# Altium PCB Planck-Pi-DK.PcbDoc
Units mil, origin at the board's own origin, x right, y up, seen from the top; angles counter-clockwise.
Board outline 1820 x 940 mil, 4 copper layers (Top1, Signal2, Gnd3, Bottom4), stack 60.449 mil thick; 99 components, 92 nets, 414 pads, 228 vias.
Unrouted connection lines stored in the file: 54.
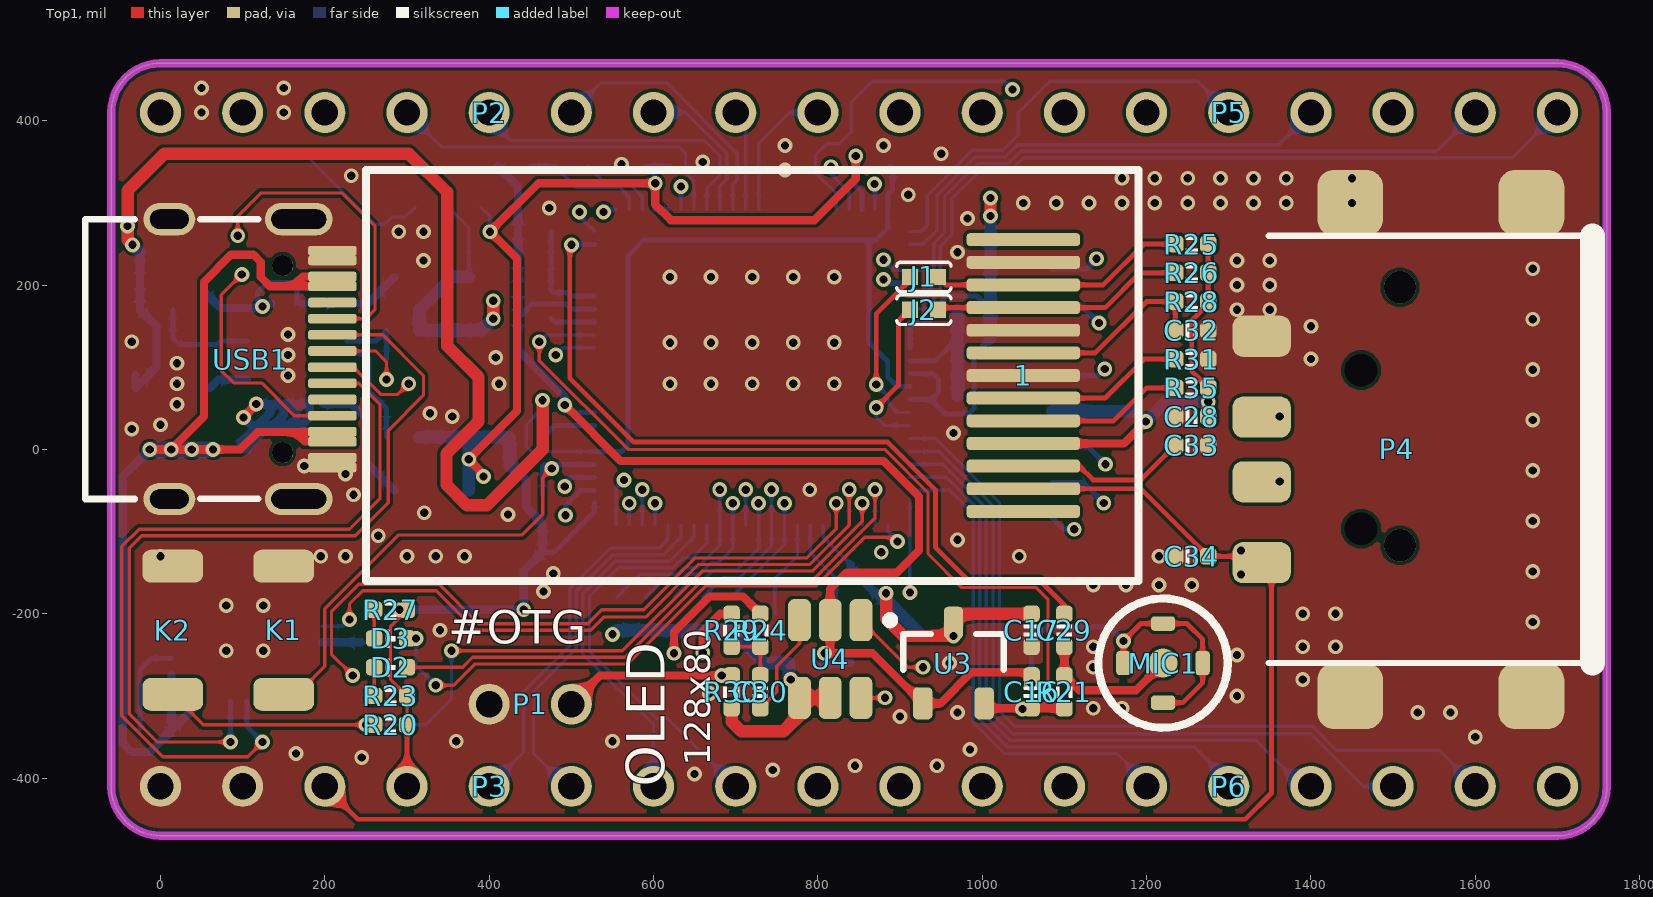
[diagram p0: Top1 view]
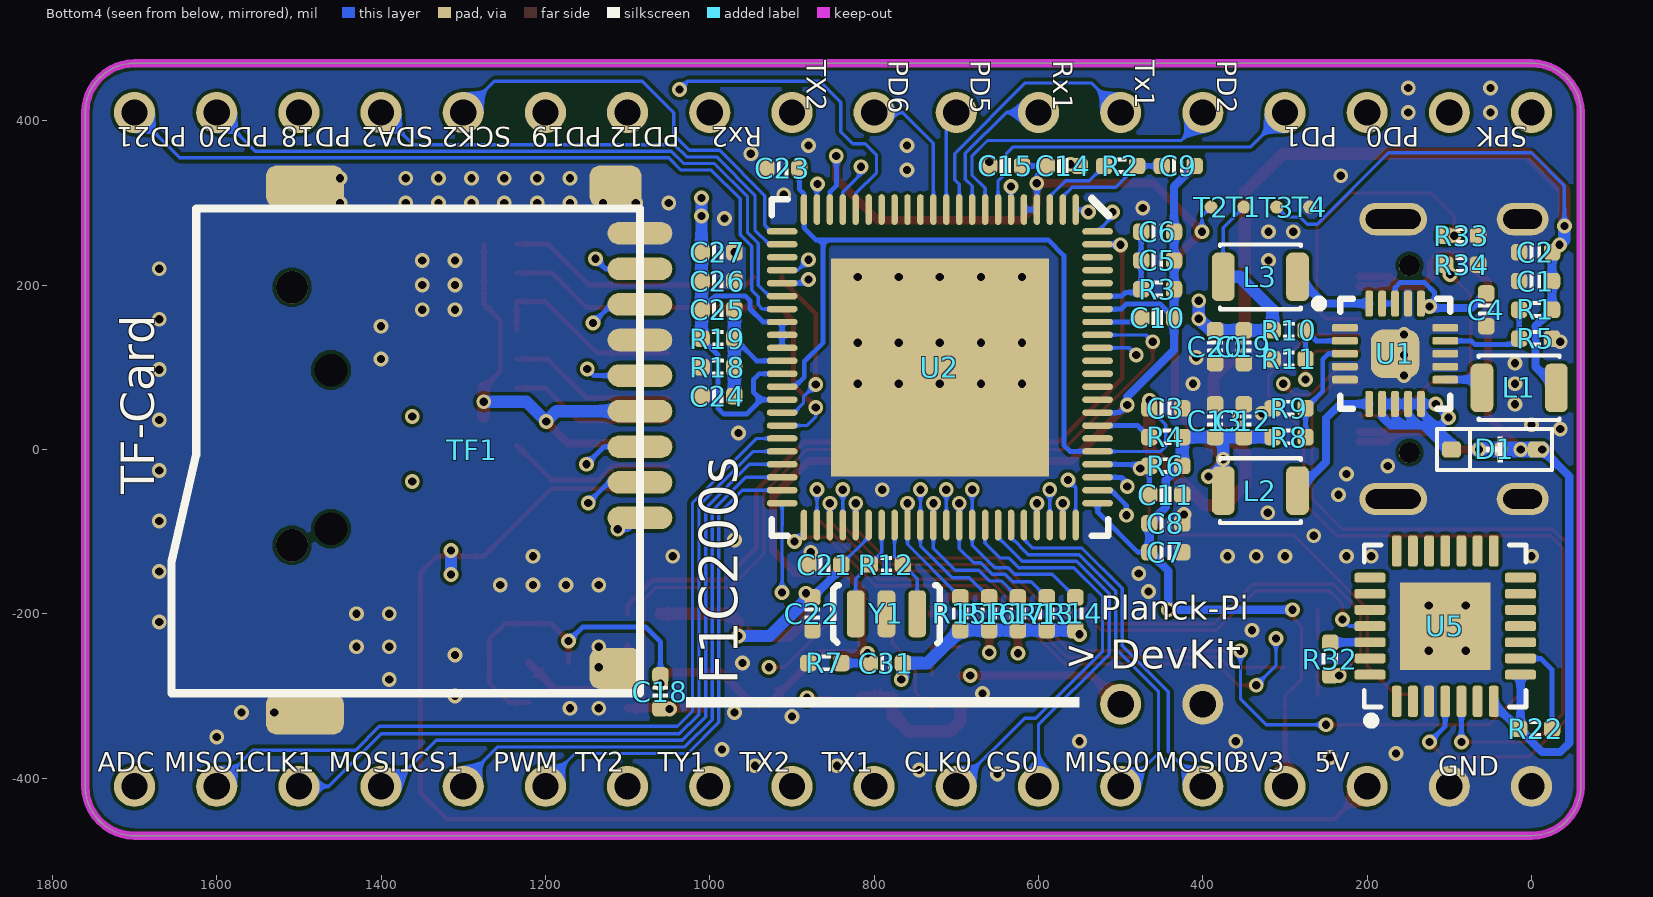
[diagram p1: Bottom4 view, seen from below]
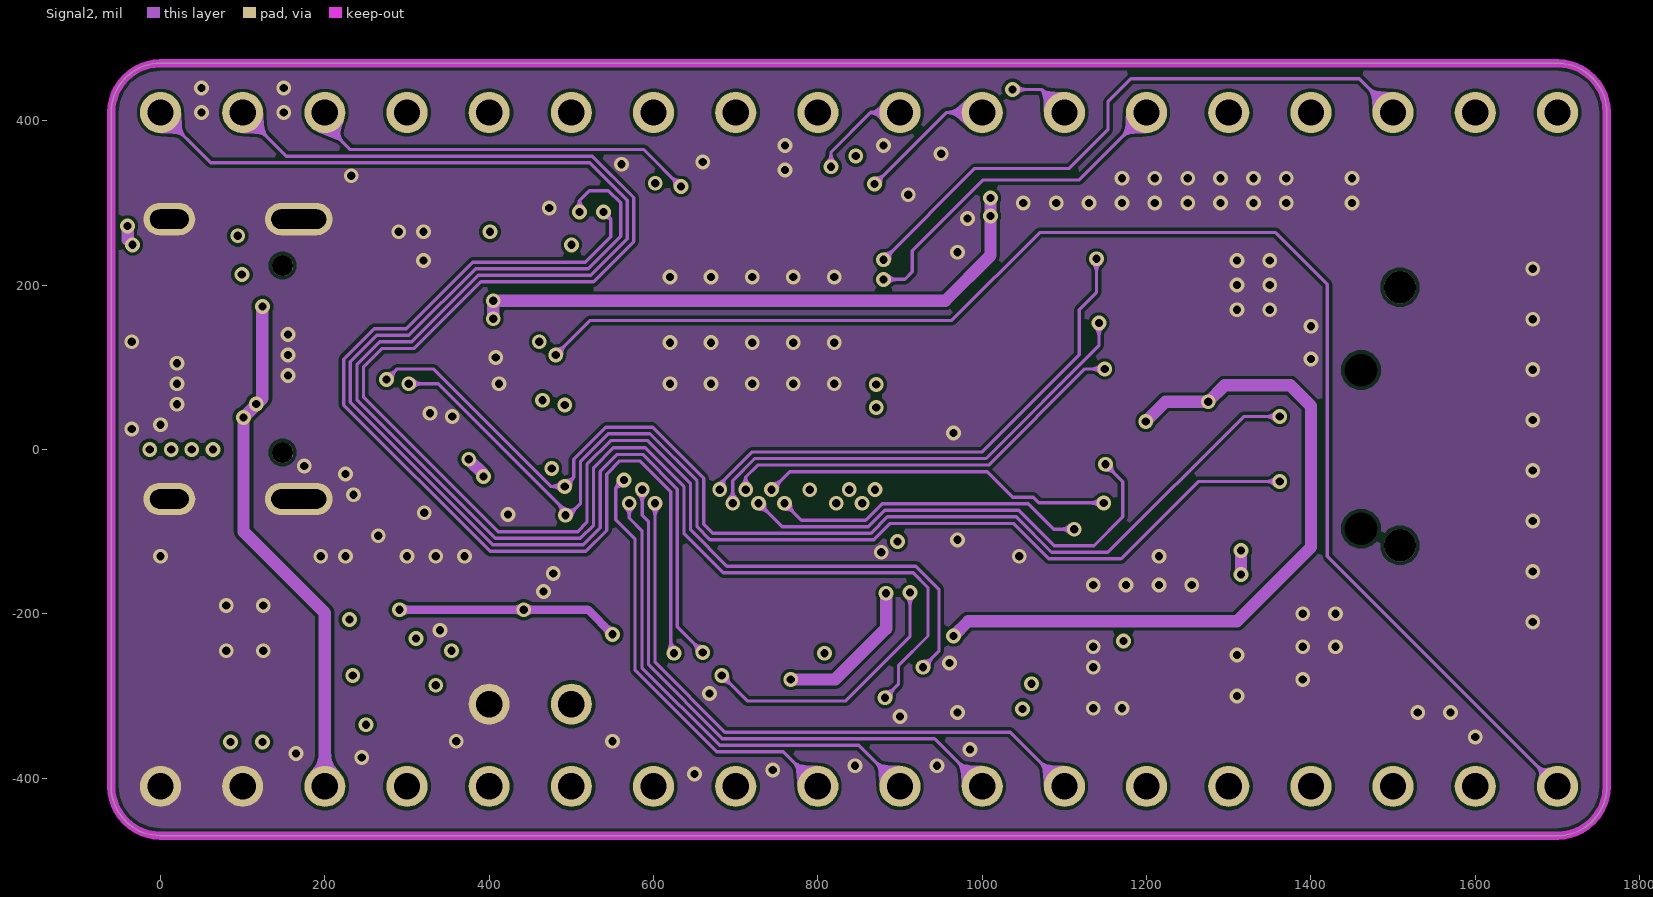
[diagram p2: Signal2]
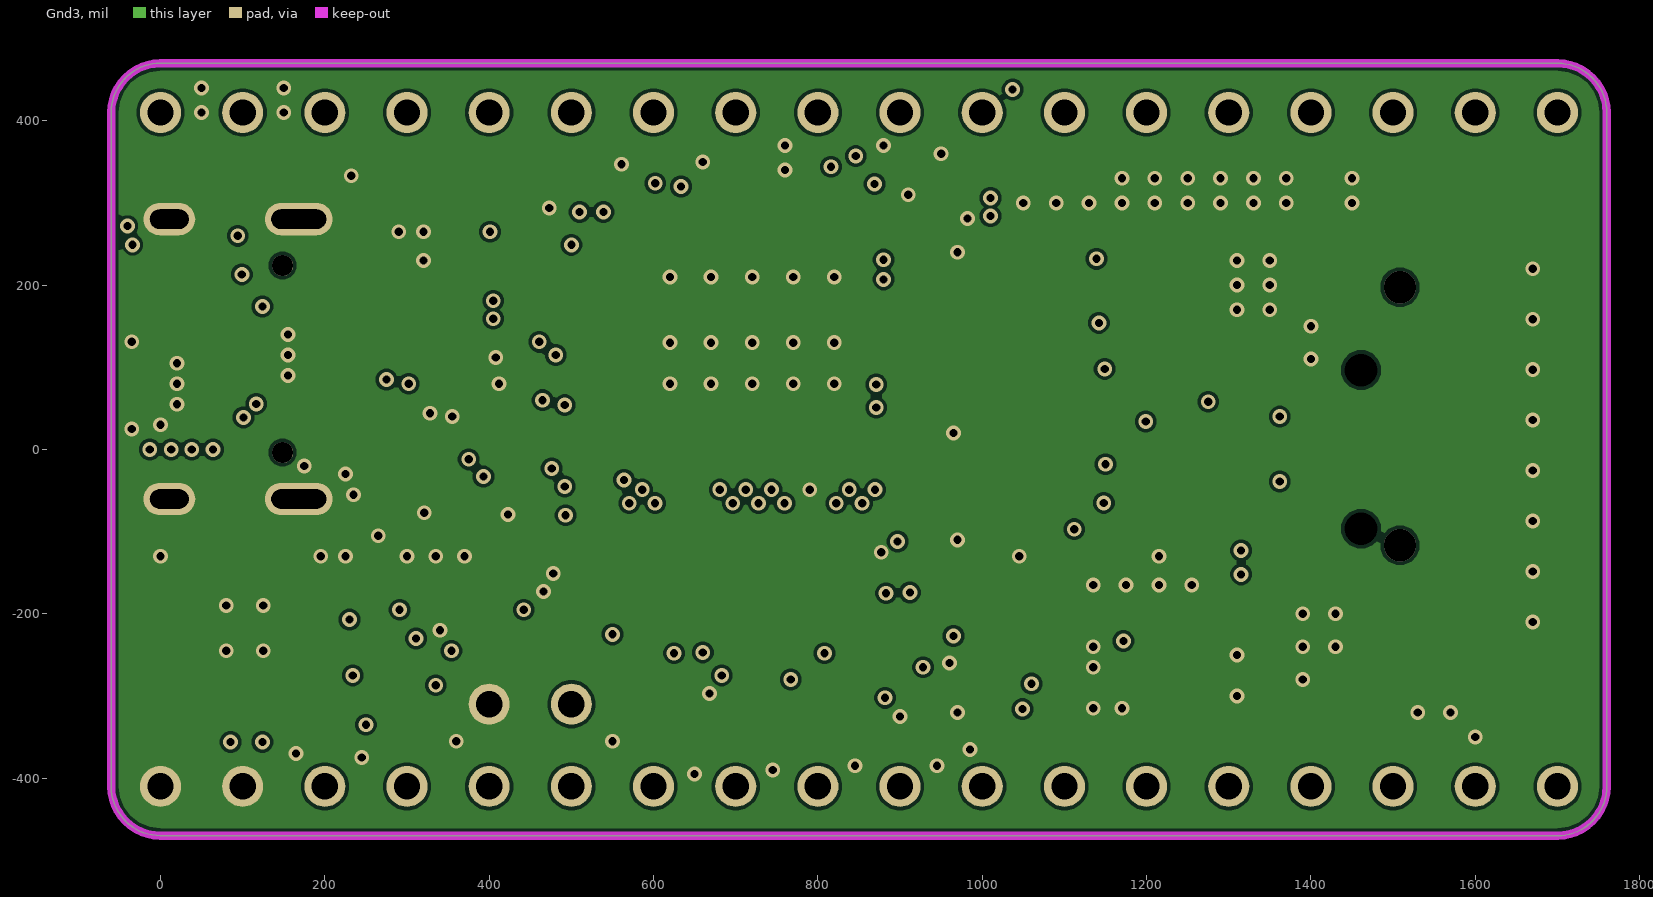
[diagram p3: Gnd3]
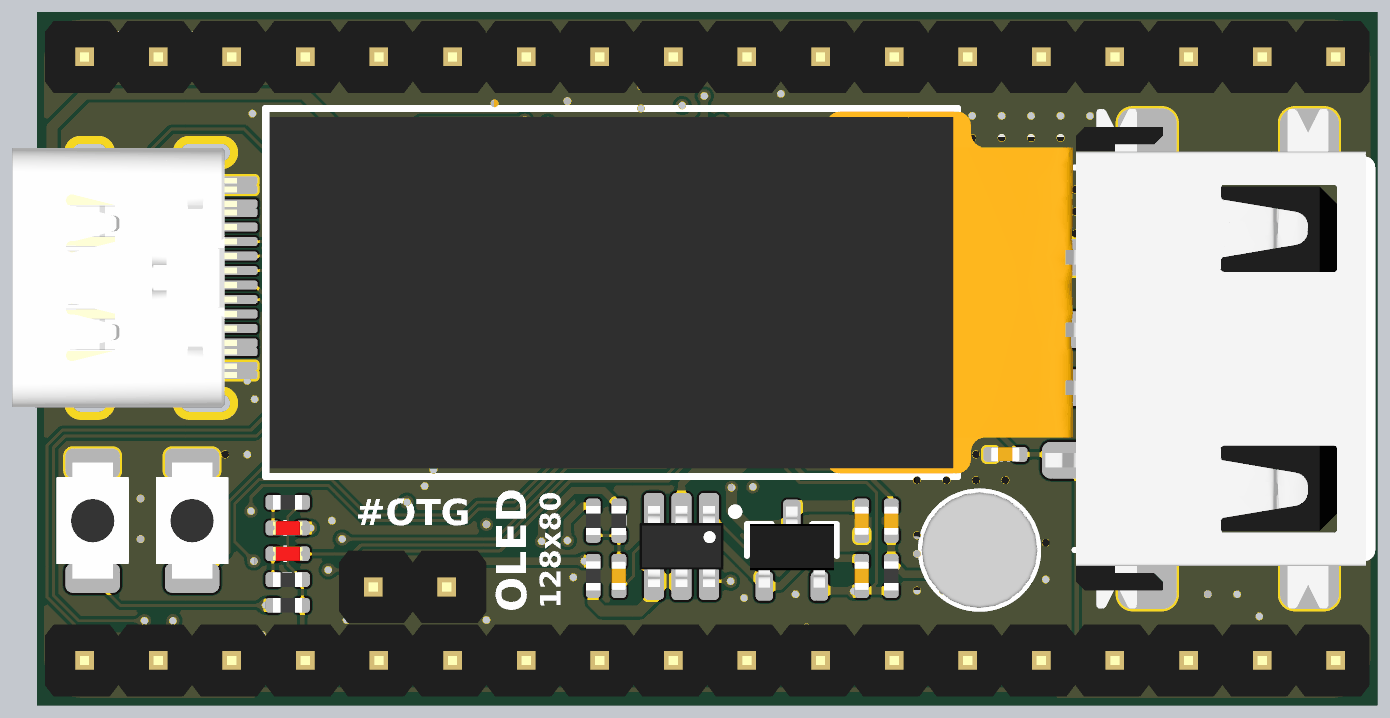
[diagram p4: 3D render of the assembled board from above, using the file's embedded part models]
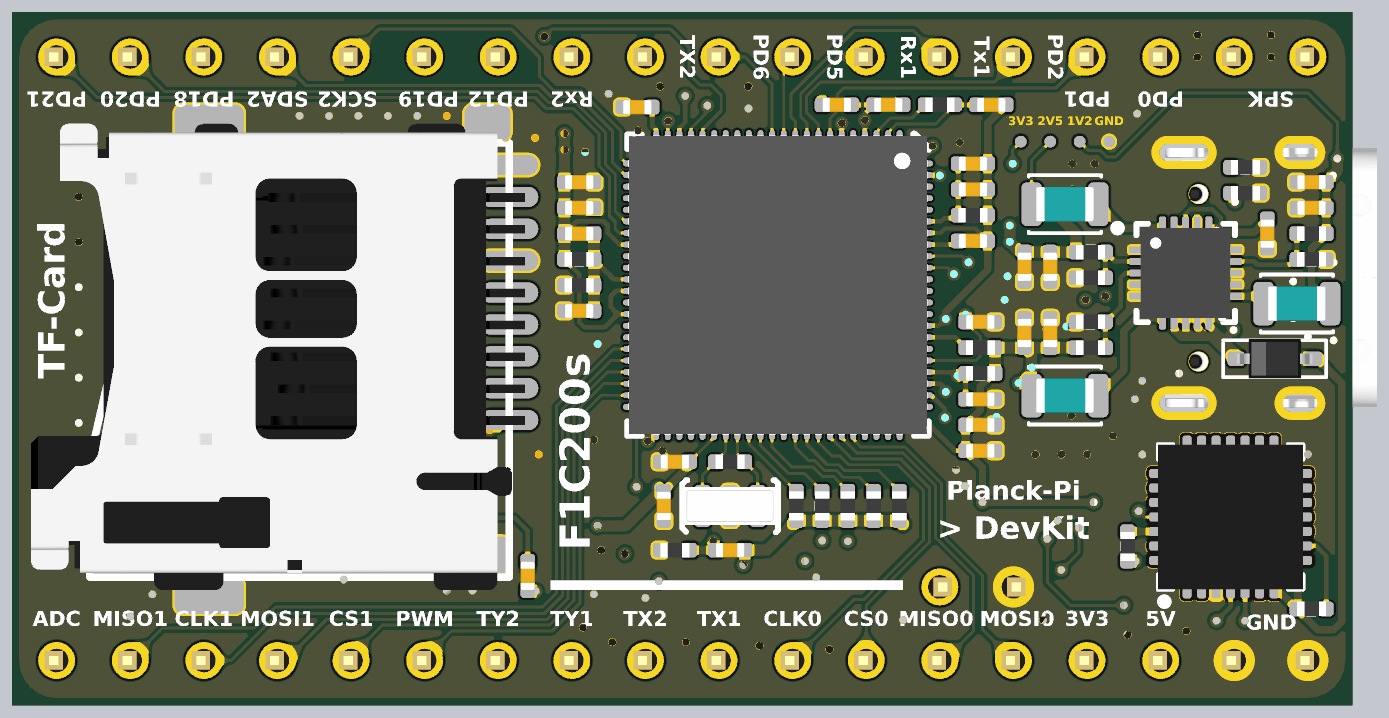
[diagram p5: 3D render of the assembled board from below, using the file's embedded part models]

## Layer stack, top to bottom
Top Solder: solder mask 0.8, Solder Resist, Dk 3.5
Top1: signal copper 0.689
Dielectric1: core 7.874, FR-4, Dk 4.2
Signal2: signal copper 0.5
Dielectric2: core 42.3228, Dk 4.2
Gnd3: signal copper 0.5
Dielectric3: prepreg 7.874, Dk 4.2
Bottom4: signal copper 0.689
Bottom Solder: solder mask 0.8, Solder Resist, Dk 3.5

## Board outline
-60,-410 -60,410 cw(c0,410) 0,470 1700,470 cw(c1700,410) 1760,410 1760,-410 cw(c1700,-410) 1700,-470 0,-470 cw(c0,-410)

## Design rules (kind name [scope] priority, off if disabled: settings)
Clearance [All] p1: gap=4 ignorepadtopadclearanceinfootprint=FALSE except(0: Arc-Hole Track-Hole SMDPad-Hole THPad-Hole Via-Hole Fill-Hole Poly-Hole Region-Hole Text-Hole)
ComponentClearance [All] p1: gap=0 collisioncheckmode=3 verticalgap=0 showdistances=FALSE
DiffPairsRouting [All] p1: maxlimit=9 minlimit=9 mostfreqgap=9 toplayer_minwidth=15 toplayer_maxwidth=15 toplayer_prefwidth=15 midlayer1_minwidth=15 midlayer1_maxwidth=15 midlayer1_prefwidth=15 midlayer2_minwidth=15 midlayer2_maxwidth=15 midlayer2_prefwidth=15 bottomlayer_minwidth=15 bottomlayer_maxwidth=15 bottomlayer_prefwidth=15 maxuncoupledlength=500
FanoutControl Fanout_BGA [All] p1: bgadir=Out bgaviamode=Centered fanoutstyle=Auto fanoutdirection=Alternating viagrid=1 // Fanout_BGA (Default Rule)
HoleSize [All] p1: absolutevalues=TRUE maxlimit=10000 minlimit=8 maxpercent=80.000 minpercent=20.000
MinimumSolderMaskSliver [All] p1 off: minsoldermaskwidth=2
PlaneClearance [All] p1: clearance=8
PlaneConnect [All] p1: planeconnectstyle=Direct reliefexpansion=20 reliefentries=4 reliefconductorwidth=10 reliefairgap=10
PolygonConnect [All] p1: connectstyle=Direct reliefconductorwidth=10 reliefentries=4 polygonreliefangle="90 Angle" airgapwidth=10
RoutingVias [All] p1: holewidth=8 width=16 viastyle="Through Hole" minholewidth=6 minwidth=12 maxholewidth=28 maxwidth=50
SilkToSilkClearance [All] p1: silktosilkclearance=0
SilkToSolderMaskClearance [IsPad] p1: minsilkscreentomaskgap=0 clearancetoexposedcopper=TRUE
SolderMaskExpansion [All] p1: expansion=3 istentingtop=FALSE
Width GND [(InNet('AGND') OR InNet('GND'))] p1: maxlimit=50 minlimit=4 preferedwidth=10
Width VCC [(InNet('VDD_SYS_3.3V') OR InNet('VDD_AV_3.3V') OR InNet('VDD_5V') OR InNet('VDD1V2-SYS') OR InNet('VDD1V1-EPHY') OR InNet('VDD-CPUX') OR InNet('VDD-CPUS') OR InNet('VDD-CPUFB') OR InNet('VCC-DRAM'))] p2: maxlimit=50 minlimit=4 preferedwidth=10
Width [All] p3: maxlimit=10000 minlimit=4 preferedwidth=4
21 further rules are at their usual default settings.

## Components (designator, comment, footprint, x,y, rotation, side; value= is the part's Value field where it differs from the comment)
1 "OLED-12880" OLED-12880 1050,90 r0 top locked
C1 "10uF" CAP_0402 -5,205 r0 bottom value=0.1u
C2 "0.1uF" CAP_0402 -5,240 r0 bottom value=0.1u
C3 "0.1uF" CAP_0402 445,50 r0 bottom value=0.1u
C4 "10uF" CAP_0402 55,170 r90 bottom value=0.1u
C5 "0.1uF" CAP_0402 455,230 r0 bottom value=0.1u
C6 "10uF" CAP_0402 455,265 r0 bottom value=0.1u
C7 "0.1uF" CAP_0402 445,-125 r180 bottom value=0.1u
C8 "10uF" CAP_0402 445,-90 r180 bottom value=0.1u
C9 "1uF" CAP_0402 430,345 r180 bottom value=0.1u
C10 "1uF" CAP_0402 455,160 r0 bottom value=0.1u
C11 "1uF" CAP_0402 445,-55 r0 bottom value=0.1u
C12 "10uF" CAP_0402 350,35 r90 bottom value=0.1u
C13 "0.1uF" CAP_0402 385,35 r90 bottom value=0.1u
C14 "10uF" CAP_0402 570,345 r0 bottom value=0.1u
C15 "0.1uF" CAP_0402 640,345 r180 bottom value=0.1u
C16 "10uF" CAP_0402 1060,-295 r270 top value=0.1u
C17 "10uF" CAP_0402 1060,-220 r270 top value=0.1u
C18 "0.1uF" CAP_0402 1060,-295 r270 bottom value=0.1u
C19 "10uF" CAP_0402 350,125 r270 bottom value=0.1u
C20 "0.1uF" CAP_0402 385,125 r270 bottom value=0.1u
C21 "0.1uF" CAP_0402 860,-140 r0 bottom value=0.1u
C22 "10uF" CAP_0402 875,-200 r270 bottom value=0.1u
C23 "0.1uF" CAP_0402 911,342 r180 bottom value=0.1u
C24 "0.1uF" CAP_0402 990,65 r180 bottom value=0.1u
C25 "0.1uF" CAP_0402 990,170 r0 bottom value=0.1u
C26 "0.1uF" CAP_0402 990,205 r0 bottom value=0.1u
C27 "10uF" CAP_0402 990,240 r180 bottom value=0.1u
C28 "10uF" CAP_0402 1255,40 r0 top value=0.1u
C29 "1uF" CAP_0402 1100,-220 r270 top value=0.1u
C30 "1uF" CAP_0402 730,-295 r90 top value=0.1u
C31 "10uF" CAP_0402 785,-260 r0 bottom value=0.1u
C32 "10uF" CAP_0402 1255,145 r180 top value=0.1u
C33 "10uF" CAP_0402 1255,5 r180 top value=0.1u
C34 "10uF" CAP_0402 1255,-130 r0 top value=0.1u
D1 "二极管-5819W" SOD-323 45,0 r0 bottom
D2 "color?" LED_0402_RED 280,-265 r0 top
D3 "color?" LED_0402_RED 280,-230 r0 top
J1 "跳线" 0402-0R 929,210 r180 top
J2 "跳线" 0402-0R 929,170 r180 top
K1 "TACT 2P" ButtonTACT_3x4x2_180 150,-220 r270 top locked value=3x4
K2 "TACT 2P" ButtonTACT_3x4x2_180 15,-220 r270 top locked value=3x4
L1 "2.2uH" 2520-L 15,75 r180 bottom
L2 "2.2uH" 2520-L 330,-50 r0 bottom
L3 "2.2uH" 2520-L 330,210 r0 bottom
MIC1 "MIC" MIC-SMT 1220,-260 r0 top locked
P1 "DIP 1x2" HDR1X2_2.54_180 400,-310 r90 top value=2.54
P2 "HDR1x9.54" HDR1X9_2.54_180 0,410 r90 top locked
P3 "HDR1x9.54" HDR1X9_2.54_180 0,-410 r90 top locked
P4 "USB-A" USB-Short 1595,0 r0 top locked
P5 "HDR1x9.54" HDR1X9_2.54_180 900,410 r90 top locked
P6 "HDR1x9.54" HDR1X9_2.54_180 900,-410 r90 top locked
R1 "100K" RES_0402 -5,170 r180 bottom value=22R
R2 "22R" RES_0402 500,345 r0 bottom
R3 "200K" RES_0402 455,195 r180 bottom value=22R
R4 "0R" RES_0402 445,15 r180 bottom value=22R
R5 "100K" RES_0402 -5,135 r0 bottom value=22R
R6 "10K" RES_0402 445,-20 r180 bottom value=22R
R7 "0R" RES_0402 860,-260 r0 bottom value=22R
R8 "510K" RES_0402 295,15 r0 bottom value=22R
R9 "110K" RES_0402 295,50 r180 bottom value=22R
R10 "95K" RES_0402 295,145 r0 bottom value=22R
R11 "30K" RES_0402 295,110 r180 bottom value=22R
R12 "1M" RES_0402 785,-140 r180 bottom value=22R
R13 "10K" RES_0402 590,-200 r90 bottom value=22R
R14 "10K" RES_0402 555,-200 r90 bottom value=22R
R15 "10K" RES_0402 695,-200 r90 bottom value=22R
R16 "10K" RES_0402 660,-200 r90 bottom value=22R
R17 "10K" RES_0402 625,-200 r90 bottom value=22R
R18 "2K" RES_0402 990,100 r0 bottom value=22R
R19 "2K" RES_0402 990,135 r180 bottom value=22R
R20 "10K" RES_0402 280,-335 r180 top value=22R
R21 "1K" RES_0402 1100,-295 r90 top value=22R
R22 "10K" RES_0402 -5,-340 r180 bottom value=22R
R23 "2K" RES_0402 280,-300 r0 top value=22R
R24 "150K" RES_0402 730,-220 r270 top value=22R
R25 "10K" RES_0402 1255,250 r0 top value=22R
R26 "10K" RES_0402 1255,215 r0 top value=22R
R27 "2K" RES_0402 280,-195 r0 top value=22R
R28 "10K" RES_0402 1255,180 r0 top value=22R
R29 "150K" RES_0402 695,-220 r270 top value=22R
R30 "47K" RES_0402 695,-295 r90 top value=22R
R31 "560K" RES_0402 1255,110 r0 top value=22R
R32 "200R" RES_0402 245,-255 r90 bottom value=22R
R33 "5.1K" RES_0402 85,260 r180 bottom value=22R
R34 "5.1K" RES_0402 85,225 r180 bottom value=22R
R35 "4.7K" RES_0402 1255,75 r0 top value=22R
T1 "测试点" TEST_PT 350,294.99 r180 bottom
T2 "测试点" TEST_PT 390,294.99 r180 bottom
T3 "测试点" TEST_PT 310,294.99 r180 bottom
T4 "测试点" TEST_PT 270,294.99 r180 bottom
TF1 "TF" TF-SOCKET 1413,-263.69 r0 bottom
U1 "EA3036" QFN-20 166.02,116.5 r180 bottom
U2 "F1C200S" QFN-88-0.4MM 720,100 r270 bottom locked
U3 "XC6206-3.0" SOT23-3 965,-260 r90 top
U4 "PAM8301" SOT23-6 815,-255 r270 top
U5 "CP2102" QFN-28 105,-215 r90 bottom value=Value
USB1 "Type-C" Type-C-TOP 110,110 r180 top locked
Y1 "24MHz" 晶振-3P 785,-200 r0 bottom

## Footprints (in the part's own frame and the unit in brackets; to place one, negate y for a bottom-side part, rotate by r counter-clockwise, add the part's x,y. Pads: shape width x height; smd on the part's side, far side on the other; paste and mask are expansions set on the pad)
0402-0R [mm] "选择焊盘"
  rect 0.5x0.5 smd: 1(-0.432,0) 2(0.432,0)
  silkscreen extent -0.84,-0.46 0.84,0.46
2520-L [mm]
  rrect50% 0.7x1.5 smd: 1(-1.15,0) 2(1.15,0)
  silkscreen extent -1.25,-1 1.25,1, body extent -1,-0.6 1,0.6, height 0.92
ButtonTACT_3x4x2_180 [mil]
  rrect50% 40x74 smd: 1(-78,0) 2(78,0)
  body extent -79,-49 79,49, height 63
CAP_0402 [mil]
  rrect50% 20x20 smd: 1(-20,0) 2(20,0)
  silkscreen extent -6,-9 6,9, body extent -20,-10 20,10, height 20
HDR1X2_2.54_180 [mil]
  round 50 hole 32: 1(0,0) 2(0,-100)
  body extent -49,-150 49,50, height 323
HDR1X9_2.54_180 [mil]
  round 50 hole 32: 1(0,0) 2(0,-100) 3(0,-200) 4(0,-300) 5(0,-400) 6(0,-500) 7(0,-600) 8(0,-700) 9(0,-800)
  body extent -49,-850 49,50, height 323
LED_0402_RED [mil]
  rrect50% 20x20 smd: 1(-20,0) 2(20,0)
  silkscreen extent -6,-10 6,10, body extent -20,-10 20,10, height 18
MIC-SMT [mm]
  rrect50% 0.45x0.75 smd: 1(-1.223,0) 1(1.223,0)
  rrect50% 0.75x0.45 smd: 1(0,-1.223) 1(0,1.223)
  round 0.9 smd: 2(0,0)
  silkscreen extent -2,-2 2,2, body extent -2,-2 2,2, height 1.35
OLED-12880 [mm]
  rrect50% 3.5x0.4 smd: 1(0,-4.2) 2(0,-3.5) 3(0,-2.8) 4(0,-2.1) 5(0,-1.4) 6(0,-0.7) 7(0,0) 8(0,0.7) 9(0,1.4) 10(0,2.1) 11(0,2.8) 12(0,3.5) 13(0,4.2)
  silkscreen extent -20.32,-6.35 3.56,6.35, body extent -20.18,-6.25 7.54,6.25, height 1.55
QFN-20 [mm] "QFN, 20-Leads, Body 3.00x3.00mm, Pitch 0.40mm, Thermal Pad 1.65x1.65mm, IPC Medium Density"
  rrect50% 0.8x0.24 smd: 1(-1.55,0.8) 2(-1.55,0.4) 3(-1.55,0) 4(-1.55,-0.4) 5(-1.55,-0.8) 11(1.55,-0.8) 12(1.55,-0.4) 13(1.55,0) 14(1.55,0.4) 15(1.55,0.8)
  rrect50% 0.24x0.8 smd: 6(-0.8,-1.55) 7(-0.4,-1.55) 8(0,-1.55) 9(0.4,-1.55) 10(0.8,-1.55) 16(0.8,1.55) 17(0.4,1.55) 18(0,1.55) 19(-0.4,1.55) 20(-0.8,1.55)
  rrect50% 1.5x1.5 smd: 21(0,0)
  silkscreen extent -2.48,-1.7 1.7,1.7, body extent -1.56,-1.56 1.56,1.56, height 0.8
QFN-28 [mil]
  rrect50% 38x12 smd mask+5: 1(-91.5,59.06) 2(-91.5,39.37) 3(-91.5,19.69) 4(-91.5,0) 5(-91.5,-19.68) 6(-91.5,-39.37) 7(-91.5,-59.06) 15(91.5,-59.06) 16(91.5,-39.37) 17(91.5,-19.68) 18(91.5,0) 19(91.5,19.69) 20(91.5,39.37) 21(91.5,59.06)
  rrect50% 12x38 smd mask+5: 8(-59.06,-91.5) 9(-39.37,-91.5) 10(-19.68,-91.5) 11(0,-91.5) 12(19.69,-91.5) 13(39.37,-91.5) 14(59.06,-91.5) 22(59.06,91.5) 23(39.37,91.5) 24(19.69,91.5) 25(0,91.5) 26(-19.68,91.5) 27(-39.37,91.5) 28(-59.06,91.5)
  rect 106.3x110.24 smd: 29(0,0)
  silkscreen extent -120,-98 98,98, body extent -99,-99 98,98, height 35
QFN-88-0.4MM [mm] "QFN, 88-Leads, Body 10.00x10.00mm, Pitch 0.40mm, Thermal Pad 6.74x6.74mm, IPC Medium Density"
  oval 0.95x0.2 smd: 1(-4.875,4.2) 2(-4.875,3.8) 3(-4.875,3.4) 4(-4.875,3) 5(-4.875,2.6) 6(-4.875,2.2) 7(-4.875,1.8) 8(-4.875,1.4) 9(-4.875,1) 10(-4.875,0.6) 11(-4.875,0.2) 12(-4.875,-0.2) 13(-4.875,-0.6) 14(-4.875,-1) 15(-4.875,-1.4) 16(-4.875,-1.8) 17(-4.875,-2.2) 18(-4.875,-2.6) 19(-4.875,-3) 20(-4.875,-3.4) 21(-4.875,-3.8) 22(-4.875,-4.2) 45(4.875,-4.2) 46(4.875,-3.8) 47(4.875,-3.4) 48(4.875,-3) 49(4.875,-2.6) 50(4.875,-2.2) 51(4.875,-1.8) 52(4.875,-1.4) 53(4.875,-1) 54(4.875,-0.6) 55(4.875,-0.2) 56(4.875,0.2) 57(4.875,0.6) 58(4.875,1) 59(4.875,1.4) 60(4.875,1.8) 61(4.875,2.2) 62(4.875,2.6) 63(4.875,3) 64(4.875,3.4) 65(4.875,3.8) 66(4.875,4.2)
  oval 0.2x0.95 smd: 23(-4.2,-4.875) 24(-3.8,-4.875) 25(-3.4,-4.875) 26(-3,-4.875) 27(-2.6,-4.875) 28(-2.2,-4.875) 29(-1.8,-4.875) 30(-1.4,-4.875) 31(-1,-4.875) 32(-0.6,-4.875) 33(-0.2,-4.875) 34(0.2,-4.875) 35(0.6,-4.875) 36(1,-4.875) 37(1.4,-4.875) 38(1.8,-4.875) 39(2.2,-4.875) 40(2.6,-4.875) 41(3,-4.875) 42(3.4,-4.875) 43(3.8,-4.875) 44(4.2,-4.875) 67(4.2,4.875) 68(3.8,4.875) 69(3.4,4.875) 70(3,4.875) 71(2.6,4.875) 72(2.2,4.875) 73(1.8,4.875) 74(1.4,4.875) 75(1,4.875) 76(0.6,4.875) 77(0.2,4.875) 78(-0.2,4.875) 79(-0.6,4.875) 80(-1,4.875) 81(-1.4,4.875) 82(-1.8,4.875) 83(-2.2,4.875) 84(-2.6,4.875) 85(-3,4.875) 86(-3.4,4.875) 87(-3.8,4.875) 88(-4.2,4.875)
  rect 6.74x6.74 smd: 89(0,0)
  silkscreen extent -5.21,-5.2 5.2,5.21, body extent -5.17,-5.17 5.17,5.17, height 1.11
RES_0402 [mil]
  rrect50% 20x20 smd: 1(-20,0) 2(20,0)
  silkscreen extent -7,-10 7,10, body extent -20,-10 20,10, height 14
SOD-323 [mm]
  rrect50% 0.6x0.5 smd: 1(-1.329,0) 2(1.329,0)
  silkscreen extent -1.78,-0.64 1.78,0.64, body extent -1.3,-0.68 1.3,0.67, height 1.15
SOT23-3 [mm] "SOT23, 3-Leads, Body 3.1x3.0mm (max), Pitch 0.95mm, IPC Medium Density"
  rrect50% 1x0.6 smd: 1(-1.246,0.95) 2(-1.246,-0.95) 3(1.246,0)
  silkscreen extent -0.2,-1.55 0.9,1.55, body extent -1.3,-1.45 1.5,1.45, height 1.2
SOT23-6 [mm]
  rrect50% 1.3x0.7 smd: 1(-1.2,0.95) 2(-1.2,0) 3(-1.2,-0.95) 4(1.2,-0.95) 5(1.2,0) 6(1.2,0.95)
  silkscreen extent -1.32,1.73 -1.08,1.98, body extent -1.4,-1.45 1.4,1.45, height 1.45
TEST_PT [mil]
  rrect100% 16x16 smd: 0(0,0.01)
TF-SOCKET [mm]
  oval 2x0.7 smd: 1(-8.331,-4.582) 2(-8.331,-5.682) 3(-8.331,-6.782) 4(-8.331,-7.882) 5(-8.331,-8.982) 6(-8.331,-10.082) 7(-8.331,-11.182) 8(-8.331,-12.282) 9(-8.331,-13.382)
  rrect50% 1.6x1.27 smd: 10(-7.577,-14.836) 10(-7.577,0.068)
  rrect50% 2.4x1.27 smd: 10(2.023,-14.836) 10(2.023,1.476)
  silkscreen extent -8.33,-14.15 6.15,0.84, body extent -8.87,-14.81 8.18,1.29, height 2.05
Type-C-TOP [mm]
  round 0.65 hole 0.65: 0(-0.98,2.89) 0(-0.98,-2.89)
  oval 1.6x1 hole 0.6 slot 1.2 at 0 deg: 1(2.52,4.325) 2(2.52,-4.325)
  oval 2.1x1 hole 0.6 slot 1.7 at 0 deg: 3(-1.48,-4.325) 4(-1.48,4.325)
  rrect50% 1.5x0.3 smd: A1(-2.52,-3.35) A4(-2.52,-2.55) A5(-2.52,-1.25) A6(-2.52,-0.25) A7(-2.52,0.25) A8(-2.52,1.25) A9(-2.52,2.55) A12(-2.52,3.35) B1(-2.52,3.05) B4(-2.52,2.25) B5(-2.52,1.75) B6(-2.52,0.75) B7(-2.52,-0.75) B8(-2.52,-1.75) B9(-2.52,-2.25) B12(-2.52,-3.05)
  silkscreen extent -0.22,-4.33 5.12,4.33, body extent -2.57,-4.48 5.18,4.48, height 3.26
USB-Short [mm]
  rrect50% 2.032x2.032 smd: 0(-3.738,-7.625) 0(-3.738,7.625) 0(1.862,-7.625) 0(1.862,7.625)
  rrect50% 1.8x1.27 smd: 1(-6.476,-3.5) 2(-6.476,-1) 3(-6.476,1) 4(-6.476,3.5)
  round 0.6 hole 1.016 unplated: MH1(-3.4,2.45) MH2(-3.4,-2.45)
  silkscreen extent -6.25,-6.6 3.75,6.6, body extent -7.25,-8.62 3.81,8.62, height 6.4
晶振-3P [mm] "贴片晶振"
  rrect50% 0.55x1.45 smd: 1(-0.95,0) 2(0,0) 3(0.95,0)
  silkscreen extent -1.65,-0.89 1.65,0.91, body extent -1.6,-0.89 1.65,0.89, height 0.7

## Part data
C1 C2 C3 C4 C5 C6 C7 C8 C9 C10 C11 C12 C13 C14 C15 C16 C17 C18 C19 C20 C21 C22 C23 C24 C25 C26 C27 C28 C29 C30 C31 C32 C33 C34: library part 电容-0402, "Capacitor"
D1: "40V"
D2 D3: library part LED_0402, "LED"
J1 J2: "Resistor"
K1 K2: library part ButtonTACT_3x4x2_180, "Button"
L1 L2 L3: library part 电感-2520, "磁珠"
P1: library part HDR1x2_2.54, "Header"
P2 P3 P5 P6: library part HDR1x9_2.54, "Header"
R1 R2 R3 R4 R5 R6 R7 R8 R9 R10 R11 R12 R13 R14 R15 R16 R17 R18 R19 R20 R21 R22 R23 R24 R25 R26 R27 R28 R29 R30 R31 R32 R33 R34 R35: library part 电阻-0402, "Resistor"
TF1: library part TF卡座, "8脚自弹"
U1: "EA3036 is a 3CH power management IC for applications powered by one Li-Ion battery or a DC 5V adapter."
U2: BOM_Manufacturer=Allwinner
U3: "LDO"
U5: "USB转TTL"
USB1: library part USB-Type-C-TOP
Y1: library part 晶振-3Pin, "村田贴片"

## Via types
v1: diameter 18, hole 10, Top1 to Bottom4, tented both sides, 226 vias
v2: diameter 39.37, hole 39.37, Top1 to Bottom4, 2 vias

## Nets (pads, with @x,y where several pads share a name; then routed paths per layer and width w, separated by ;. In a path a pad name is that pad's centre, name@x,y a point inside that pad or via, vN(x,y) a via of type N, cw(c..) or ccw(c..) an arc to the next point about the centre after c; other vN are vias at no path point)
#RESET: C11.2 K1.2 R6.1 U2.70 | length 606.1
  Top1 w4: K1.2 166,-298 200,-264 200,-194 290,-104 440,-104 465,-79 465,-34 v1(476,-23)
  Bottom4 w6: C11.2 R6.1 466.89,-18.11 U2.70
ADC0: P6.9 U2.79 | length 1804.4
  Signal2 w4: v1(481,115) 523,157 963,157 1070,264 1357,264 1420,201 1420,-130 1636,-346 1676,-386 P6.9
  Bottom4 w4: v1(481,115) 489.62,123.62 U2.79
AGND: C5.1 C6.1 C9.2 C10.1 C16.1 C18.1 C31.2 MIC1.1 R3.2 R7.1 U2.74 U2.82 U3.1 U4.2 | length 1976.6
  Top1 w6: MIC1.1@1171.85,-260 v1(1171.85,-233.15) 1193.15,-211.85 1220,-211.85 1248.85,-211.85 1268.15,-231.15 1268.15,-260 1268.15,-283.85 1243.85,-308.15 MIC1.1@1220,-308.15
  Top1 w10: v1(492,54) 560,-14 879.72,-14 923,-57.28 923,-123 896,-150 835,-150 815,-170 U4.2 815,-241 v1(808,-248) 866.54,-248 U3.1 948.94,-309.06 987,-271 1056,-271 C16.1
  Bottom4 w6: C10.1 452,177 493,177 499.13,170.87 U2.82 ; v1(492,54) 501.12,44.88 U2.74 ; v1(1060,-285) C18.1 1060,-234 1078,-216 1154.69,-216 v1(1171.85,-233.15)
  Bottom4 w10: C9.2 435,320 C6.1 C5.1 R3.2 C10.1 435,121 492,64 v1(492,54) ; C31.2 R7.1
AUDIO_L: R24.1 U2.1 | length 1422
  Top1 w10: v1(625,-248) 625,-222 668,-179 709,-179 R24.1
  Signal2 w4: v1(539,289) 548,280 548,259 517,228 380.06,228 299.06,147 260,147 223,110 223,54 401,-124 517.63,-124 543,-98.63 543,-30 559,-14 583.43,-14 621,-51.57 621,-244 v1(625,-248)
  Bottom4 w4: v1(539,289) 541.93,291.93 U2.1
AUDIO_R: R29.1 U2.88 | length 1442.7
  Top1 w10: v1(660,-247) 660,-221 681,-200 R29.1
  Signal2 w4: v1(510,289) 510,303 522,315 545,315 560,300 560,259.69 520.31,220 383.37,220 302.37,139 263.31,139 231,106.69 231,57.31 404.31,-116 514.31,-116 535,-95.31 535,-26.69 555.69,-6 586.75,-6 629,-48.25 629,-216 v1(660,-247)
  Bottom4 w4: v1(510,289) 510,283.43 U2.88
AVCC_3V0: C16.2 C18.2 R21.1 U2.80 U3.2 | length 1113.2
  Top1 w4: v1(461,131) 461,108 569,0 881.27,0 934,-52.73 934,-126.66 975.34,-168 1066,-168 1080,-182 1080,-305 1070,-315
  Top1 w10: U3.2 1008.35,-315 1049,-315 C16.2 1070,-315 R21.1
  Bottom4 w4: v1(461,131) 469.37,139.37 U2.80
  other v1: 1049,-316
GND: 1.7 1.9 1.12 C1.2 C2.2 C3.1 C4.1 C7.2 C8.2 C11.1 C12.2 C13.2 C14.1 C15.1 C17.2 C19.2 C20.2 C21.2 C22.2 C23.1 C24.1 C26.1 C27.2 C28.1 C32.1 C33.1 C34.1 K1.1 K2.1 P1.1 P3.1 P3.2 P4.0 P4.4 R5.1 R7.2 R9.1 R11.1 R18.2 R31.2 R33.2 R34.2 T4.0 TF1.6 TF1.9 TF1.10 U1.1 U1.4 U1.5 U1.12 U1.13 U1.15 U1.17 U1.21 U2.89 U5.3 U5.29 USB1.1 USB1.2 USB1.3 USB1.4 USB1.A1 USB1.A12 USB1.B1 USB1.B12 Y1.2
  other v1: 650,-395 745,-390 845,-385 945,-385 245,-375 165,-370 985,-365 360,-355 550,-355 1600,-350 900,-325 970,-320 1530,-320 1570,-320 1135,-315 1170,-315 1310,-300 668,-297 1390,-280 1135,-265 960,-260 1310,-250 80,-245 125,-245 1135,-240 1390,-240 1430,-240 340,-220 1670,-210 1390,-200 1430,-200 80,-190 125,-190 466,-173 1135,-165 1175,-165 1215,-165 1255,-165 478,-151 1670,-148.57 0,-130 195,-130 225,-130 300,-130 335,-130 370,-130 1045,-130 1215,-130 877,-125 970,-110 265,-105 1670,-87.14 423,-79 321,-77 235,-55 790,-49 225,-30 1670,-25.71 175,-20 965,20 -35,25 0,30 1670,35.71 355,40 328,44 20,55 20,80 412,80 620,80 670,80 720,80 770,80 820,80 155,90 1670,97.14 20,105 1400,110 408,112 155,115 620,130 670,130 720,130 770,130 820,130 -35,131 155,140 1400,150 1670,158.57 1310,170 1350,170 1310,200 1350,200 620,210 670,210 720,210 770,210 820,210 1670,220 320,230 1310,230 1350,230 970,240 290,265 320,265 982,281 473,294 1050,300 1090,300 1130,300 1170,300 1210,300 1250,300 1290,300 1330,300 1370,300 1450,300 910,310 1170,330 1210,330 1250,330 1290,330 1330,330 1370,330 1450,330 232,333 760,340 561,347 660,350 950,360 760,370 880,370 50,410 150,410 50,440 150,440
HPCOM: R2.2 U2.3 | length 97.5
  Bottom4 w4: R2.2 538,327 567,327 586.14,307.86 U2.3
HPCOMFB: C9.1 R2.1 U2.2 | length 151.6
  Bottom4 w4: R2.1 506,319 559,319 570.39,307.61 U2.2
  Bottom4 w6: C9.1 R2.1
I2C0_SCK: J2.2 U2.38 | length 195
  Top1 w6: v1(871,51) 898,78 898,156 J2.2@913.83,171.83
  Bottom4 w4: v1(871,51) 871,40 881.87,29.13 U2.38
I2C0_SDA: J1.2 U2.37 | length 207.7
  Top1 w6: v1(871,79) 871,165 912,206 J1.2
  Bottom4 w4: v1(871,79) 886,64 886,56 897.12,44.88 U2.37
I2C2_SCK: P5.5 U2.23 | length 516.4
  Bottom4 w4: U2.23 925.64,265.35 933,272.71 933,308.94 988.06,364 1024.75,364 1044,383.25 1044,410 1082,448 1262,448 P5.5
I2C2_SDA: P5.6 U2.24 | length 579.5
  Bottom4 w4: U2.24 927.57,249.61 945,267.04 945,309.63 991.37,356 1028.06,356 1043.06,371 1361,371 1383.08,393.08 P5.6
KEY: K2.2 R20.2 U2.47 | length 1050
  Top1 w4: K2.2 52,-335 v1(250,-335) R20.2 ; v1(354,-245) 562,-245 659,-148 793.37,-148 853.86,-87.51 v1(853.86,-65.36)
  Bottom4 w4: v1(250,-335) 323,-335 354,-304 v1(354,-245) ; U2.47 v1(853.86,-65.36)
LED_SYS: D2.2 U2.46 | length 722.2
  Top1 w4: D2.2 367.69,-265 379.69,-253 565.31,-253 660.31,-158 794.69,-158 869.61,-83.08 v1(869.61,-48.89)
  Bottom4 w4: U2.46 v1(869.61,-48.89)
LED_USER: D3.2 U2.45 | length 730.5
  Top1 w4: v1(335,-287) 357,-287 383,-261 568.63,-261 663.63,-166 798,-166 857,-107 892,-107 v1(897,-112)
  Bottom4 w4: v1(311,-230) 311,-263 v1(335,-287) ; U2.45 885.35,-100.35 v1(897,-112)
MIC_IN: C29.1 U2.87 | length 958.6
  Top1 w6: v1(500,249) 498,247 498,86.73 575.73,9 885,9 943,-49 943,-119 983,-159 1069.73,-159 1100,-189.27 C29.1
  Bottom4 w6: v1@500.61,249.61 U2.87
Net1_3: 1.3 C33.2 | length 209.3
  Top1 w6: 1.3 1118.24,-20.24 1135,-37 1193,-37 C33.2
Net1_5: 1.5 R35.1 | length 201.6
  Top1 w6: 1.5 1159.88,34.88 1200,75 R35.1
Net1_6: 1.6 R31.1 | length 204.7
  Top1 w6: 1.6 1149.44,62.44 1197,110 R31.1
Net1_8: 1.8 C32.2 R28.1 | length 245.9
  Top1 w6: 1.8 1137.56,117.56 1200,180 R28.1 C32.2
NetC5_2: C5.2 C6.2 R3.1 U2.83 | length 126.5
  Bottom4 w6: C6.2 C5.2 R3.1 478.93,191.07 494,191.07 498.45,186.61 U2.83
NetC10_2: C10.2 U2.81 | length 55.1
  Bottom4 w6: C10.2 479.88,155.12 U2.81
NetC24_2: C24.2 C25.1 R18.1 R19.2 U2.33 | length 174.3
  Bottom4 w6: U2.33 942.87,107.87 R19.2
  Bottom4 w15: C24.2 R18.1 R19.2 C25.1
NetC29_2: C29.2 MIC1.2 R21.2 | length 176.1
  Top1 w10: C29.2 R21.2 1118,-293 1187,-293 MIC1.2
NetC30_1: C30.1 U4.3 | length 127
  Top1 w4: C30.1 750,-295 750,-264 777.6,-236.4 U4.3
NetC30_2: C30.2 R24.2 R29.2 | length 70
  Top1 w4: R29.2 R24.2 C30.2
NetD2_1: D2.1 R23.1 | length 35
  Top1 w4: R23.1 D2.1
NetD3_1: D3.1 R27.1 | length 35
  Top1 w4: D3.1 R27.1
NetL1_1: L1.1 U1.11 | length 48.9
  Bottom4 w10: L1.1 70.28,85 U1.11
NetL2_1: L2.1 U1.6 | length 162.1
  Bottom4 w10: U1.6 232.53,55.47 250,38 250,-15.28 L2.1
NetL3_1: L3.1 U1.20 | length 100.7
  Bottom4 w10: U1.20 252.24,177.52 L3.1
NetR1_1: R1.1 R5.2 U1.14 | length 129.7
  Bottom4 w6: R1.1 R5.2 22,128 69,128 73.24,132.24 U1.14
NetR4_1: R4.1 U2.73 | length 68.9
  Bottom4 w6: R4.1 479.13,29.13 U2.73
NetR8_1: R8.1 R9.2 U1.3 | length 133.3
  Bottom4 w6: U1.3 247.5,116.5 254,110 254,71 R9.2 R8.1
NetR10_1: R10.1 R11.2 U1.2 | length 88.2
  Bottom4 w6: U1.2 262.24,132.24 R10.1 R11.2
NetR12_1: R12.1 U2.51 Y1.3 | length 121.1
  Bottom4 w4: U2.51 790.87,-125.87 R12.1 822.4,-157.4 Y1.3
NetR12_2: R12.2 U2.52 Y1.1 | length 119.5
  Bottom4 w4: Y1.1 747.6,-157.4 R12.2 775.12,-129.88 U2.52
NetR22_2: R22.2 U5.9 | length 116.1
  Bottom4 w6: R22.2 -25,-268 -11.37,-254.37 U5.9
NetR32_2: R32.2 U5.26 | length 48.2
  Bottom4 w10: U5.26 R32.2@244.69,-234.68
NetR33_1: R33.1 USB1.A5 | length 377.4
  Top1 w4: v1(94,260) 94,284 122,312 221,312 261,272 261,170 250.21,159.21 USB1.A5
NetR34_1: R34.1 USB1.B5 | length 285.3
  Top1 w4: v1(99,213) 74,188 74,96 89,81 123,81 162.9,41.1 USB1.B5
OLED_SCL: 1.10 J2.1 R26.1 | length 306.5
  Top1 w6: J2.1@946,172.68 1.10 1149.68,172.68 1192,215 R26.1
OLED_SDA: 1.11 J1.1 R25.1 | length 313.7
  Top1 w6: J1.1 955.76,200.24 1.11 1147.24,200.24 1197,250 R25.1
PD0: P2.3 U2.6 | length 506.9
  Signal2 w4: P2.3 205,405 205,391 231,365 588.39,365 v1(633.39,320)
  Bottom4 w4: U2.6 v1(633.39,320)
PD1: P2.4 U2.7 | length 432
  Bottom4 w4: P2.4 342,368 631,368 639,360 639,337 649.13,326.87 U2.7
PD2: P2.5 U2.8 | length 379.4
  Bottom4 w4: P2.5 400,402 426,376 662,376 681,357 681,334 664.88,317.88 U2.8
PD5: P2.8 U2.11 | length 123.1
  Bottom4 w4: P2.8 700,400 712.13,387.87 712.13,319.13 U2.11
PD6: P2.9 U2.12 | length 168.4
  Bottom4 w4: U2.12 727.87,372.87 765,410 P2.9
PD12: P5.3 U2.18 | length 453.7
  Signal2 w4: v1(1037,438) 1072,438 P5.3
  Bottom4 w4: U2.18 822.36,311.64 797,337 797,358 811,372 826,372 840.77,386.77 840.77,422.77 866,448 1027,448 v1(1037,438)
PD17: U2.25
PD18: P5.7 U2.26 | length 800.1
  Signal2 w4: v1(880,231) 991,342 1106,342 1153,389 1153,423 1181,451 1459,451 P5.7
  Bottom4 w4: v1(880,231) 892.89,218.11 U2.26@926.69,218.11
PD19: P5.4 U2.27 | length 453.2
  Signal2 w4: v1(880,207) 906,207 915,216 915,242 1001,328 1118,328 1196,406 P5.4
  Bottom4 w6: v1(880,207) 884.64,202.36 U2.27
PD20: P5.8 U2.28 | length 835.8
  Bottom4 w4: U2.28 927.61,186.61 941,200 941,250.73 954,263.73 954,307.31 994.69,348 1031.69,348 1046.69,363 1553,363 P5.8
PD21: P5.9 U2.29 | length 949.8
  Bottom4 w4: U2.29 935.87,170.87 941,176 941,186 949,194 949,247.41 963,261.41 963,305 998,340 1035,340 1050,355 1645,355 P5.9
PWM1: P6.4 U2.43 | length 588.5
  Bottom4 w4: U2.43 960.61,-49.61 989,-78 989,-332 1027,-370 1164,-370 1200,-406 P6.4
SDC0_CLK: TF1.5 U2.56 | length 617.1
  Signal2 w4: v1(712.13,-48.89) 712.13,-33.5 726.63,-19 1008,-19 1125,98 v1(1149,98)
  Bottom4 w4: U2.56 v1(712.13,-48.89)
  Bottom4 w6: TF1.5 1140.92,89.92 v1(1149,98)
SDC0_CMD: R17.2 TF1.3 U2.55 | length 824.5
  Signal2 w4: v1(727.87,-65.36) 756.51,-94 861.37,-94 881.37,-74 1044.63,-74 1087.63,-117 1136,-117 1171,-82 1171,-39 v1(1150,-18)
  Bottom4 w4: R17.2 644.98,-160.02 659.61,-160.02 672.63,-147 701,-147 727.87,-120.13 U2.55 v1(727.87,-65.36)
  Bottom4 w6: TF1.3 1128.69,3.31 v1(1150,-18)
SDC0_D0: R13.2 TF1.7 U2.57 | length 821.3
  Signal2 w4: v1(696.38,-65.36) 696.38,-37.94 723.31,-11 1004.69,-11 1142,126.31 v1(1142,154)
  Bottom4 w4: R13.2 609,-161 631.31,-161 640.31,-152 656.31,-152 670.31,-138 679,-138 696.38,-120.62 U2.57 v1(696.38,-65.36)
  Bottom4 w6: TF1.7 1119.47,176.53 v1(1142,154)
SDC0_D1: R14.2 TF1.8 U2.58 | length 913.3
  Signal2 w4: v1(680.63,-48.89) 680.63,-42.37 720,-3 1000,-3 1118,115 1118,170 1139,191 v1(1139,232)
  Bottom4 w4: R14.2 583,-152 629,-152 637,-144 653,-144 680.63,-116.37 U2.58 v1(680.63,-48.89)
  Bottom4 w6: TF1.8 1126.84,219.84 v1(1139,232)
SDC0_D2: R15.2 TF1.1 U2.53 | length 556.3
  Signal2 w4: v1(759.37,-65.36) 780.01,-86 858.06,-86 878.06,-66 1056,-66 1087,-97 v1(1112,-97)
  Bottom4 w4: R15.2 759.37,-115.63 U2.53 v1(759.37,-65.36)
  Bottom4 w6: TF1.1 1098.69,-97 v1(1112,-97)
SDC0_D3: R16.2 TF1.2 U2.54 | length 680.6
  Signal2 w4: v1(743.62,-48.89) 765.51,-27 1006,-27 1037,-58 1062,-58 1069,-65 v1(1148,-65)
  Bottom4 w4: R16.2 684,-156 705,-156 743.62,-117.38 U2.54 v1(743.62,-48.89)
  Bottom4 w6: TF1.2 1123,-40 v1(1148,-65)
SPI0_CLK: P3.8 U2.59 | length 504.7
  Bottom4 w4: U2.59 664.88,-114.12 647,-132 636,-132 624,-144 556.94,-144 522,-178.94 522,-245.69 603.26,-326.94 616.94,-326.94 P3.8
SPI0_CS: P3.7 U2.60 | length 448.5
  Bottom4 w4: P3.7 600,-335 514,-249 514,-175.63 553.63,-136 620,-136 649.13,-106.87 U2.60
SPI0_MISO: P3.6 U2.61 | length 451.3
  Bottom4 w4: P3.6 494,-410 454,-370 454,-294.31 506,-242.31 506,-172.31 550.31,-128 612.31,-128 633.39,-106.93 U2.61
SPI0_MOSI: P3.5 U2.62 | length 443.4
  Bottom4 w4: P3.5 442,-368 442,-295 498,-239 498,-169 547,-120 607,-120 617.64,-109.36 U2.62
SPI1_CLK: P6.7 U2.40 | length 905.7
  Bottom4 w4: U2.40 947.3,-2.36 1013,-68.06 1013,-322.06 1036.94,-346 1399.69,-346 1463.69,-410 P6.7
SPI1_CS: P6.5 U2.42 | length 696.2
  Bottom4 w4: U2.42 956.17,-33.86 997,-74.69 997,-328.69 1030.31,-362 1258,-362 1300,-404 P6.5
SPI1_MISO: P6.8 U2.39 | length 1012.2
  Bottom4 w4: U2.39 942.87,13.39 1021,-64.75 1021,-318.75 1039.25,-337 1402,-337 1431,-366 1556,-366 1572,-382 P6.8
SPI1_MOSI: P6.6 U2.41 | length 799.2
  Bottom4 w4: U2.41 951.74,-18.11 1005,-71.37 1005,-325.37 1033.63,-354 1333,-354 1389,-410 P6.6
SPK_N: P2.2 U4.1 | length 2166.5
  Top1 w4: U4.1 909.65,-265 v1(928,-265)
  Signal2 w4: P2.2 153,357 525.63,357 576,306.63 576,253 527,204 390,204 309,123 269.94,123 247,100.06 247,63.94 410.94,-100 507.69,-100 519,-88.69 519,-18.25 548.25,11 592.37,11 645,-41.63 645,-97.63 689.37,-142 919.31,-142 947.34,-170.03 947.34,-245.66 v1(928,-265)
SPK_P: P2.1 U4.6 | length 2234.8
  Top1 w4: U4.6 v1(881.76,-302.24)
  Signal2 w4: P2.1 61,349 522.31,349 568,303.31 568,256.31 523.69,212 386.69,212 305.69,131 266.63,131 239,103.37 239,60.63 407.63,-108 511,-108 527,-92 527,-22 551,2 590.06,2 637,-44.94 637,-102 685,-150 916,-150 934,-168 934,-227 898,-263 898,-286 v1(881.76,-302.24)
TOUCH_X1: P3.9 U2.66 | length 585.3
  Signal2 w4: v1(564,-37) 554,-47 554,-85.47 577.53,-109 577.53,-268.53 677,-368 758,-368 P3.9
  Bottom4 w4: U2.66 554.65,-46.35 v1(564,-37)
TOUCH_X2: P6.1 U2.65 | length 607.1
  Signal2 w4: v1(570.39,-65.36) 570.39,-83.39 585.89,-98.89 585.89,-265.58 680.31,-360 850,-360 P6.1
  Bottom4 w4: U2.65 v1(570.39,-65.36)
TOUCH_Y1: P6.2 U2.64 | length 726.9
  Signal2 w4: v1(586.14,-48.89) 586.14,-80.14 593.89,-87.89 593.89,-262.26 683.63,-352 942,-352 P6.2
  Bottom4 w4: U2.64 v1(586.14,-48.89)
TOUCH_Y2: P6.3 U2.63 | length 780.8
  Signal2 w4: v1(601.89,-65.36) 601.89,-258.95 686.94,-344 1034,-344 P6.3
  Bottom4 w4: U2.63 v1(601.89,-65.36)
UART0_RX: R32.1 U2.49 | length 842
  Top1 w4: v1(234,-275) 208,-249 208,-197.31 241.31,-164 339,-164 387,-212 520,-212 537,-195 588,-195 651,-132 786.75,-132 822.36,-96.38 v1(822.36,-65.36)
  Bottom4 w4: U2.49 v1(822.36,-65.36)
UART0_TX: U2.48 U5.25 | length 829.6
  Top1 w4: v1(230,-207) 230,-188 246,-172 335.69,-172 383.69,-220 523.31,-220 539.31,-204 590.31,-204 654.31,-140 790.06,-140 838.11,-91.95 v1(838.11,-48.89)
  Bottom4 w4: U5.25 222,-215 v1(230,-207) ; U2.48 v1(838.11,-48.89)
UART1_RX: P2.7 U2.9 | length 181.4
  Bottom4 w4: P2.7 639.31,410 689,360.31 689,329 680.63,320.63 U2.9
UART1_TX: P2.6 U2.10 | length 322.9
  Bottom4 w4: P2.6 536,446 616,446 702,360 702,328.37 696.38,322.75 U2.10
UART2_RX: P5.2 U2.21 | length 198.4
  Signal2 w4: v1(869,323) 956,410 P5.2
  Bottom4 w4: v1(869,323) 869.61,322.39 U2.21
UART2_TX: P5.1 U2.19 | length 183.1
  Signal2 w4: v1(816,344) 816,362 864,410 P5.1
  Bottom4 w4: v1(816,344) 816,335 838.11,312.89 U2.19
USB_DM: P4.2 U2.68 USB1.A7 | length 1518
  Top1 w4: USB1.A7 234.84,100.16 268,67 289,67 v1(302,80)
  Signal2 w4: v1(302,80) 338,80 493,-75 v1(493,-80) 497,-80 511,-66 511,-14.94 544.94,19 595.69,19 653,-38.31 653,-94.31 668.69,-110 868,-110 888,-90 1038,-90 1081,-133 1169,-133 1263,-39 v1(1362,-39)
  Bottom4 w6: v1(493,-80) 493,-68 511.39,-49.61 U2.68
USB_DM_CP: U5.5 USB1.B7 | length 1030.4
  Top1 w4: v1(85.32,-356) -3.69,-356 -38,-321.69 -38,-120.31 -22.69,-105 237,-105 277,-65 277,23 320,66 320,90 270.47,139.53 USB1.B7
  Bottom4 w6: v1(85.32,-356) U5.5
USB_DP: P4.3 U2.69 USB1.A6 | length 1511.4
  Top1 w4: USB1.A6 262.16,119.84 275,107 v1(275,85)
  Signal2 w4: v1(275,85) 288,98 332,98 475,-45 v1(492,-45) 503,-34 503,-11.63 541.63,27 599,27 661,-35 661,-91 672,-102 864.69,-102 884.69,-82 1041.31,-82 1084.31,-125 1153,-125 1318,40 v1(1362,40)
  Bottom4 w6: v1(492,-45) 492,-41 499.14,-33.86 U2.69
USB_DP_CP: U5.4 USB1.B6 | length 983.9
  Top1 w4: v1(124,-356) 106,-374 3,-374 -47,-324 -47,-118 -26,-97 230,-97 267,-60 267,55 241.53,80.47 USB1.B6
  Bottom4 w6: U5.4 105,-337 v1(124,-356)
USB_ID: P1.2 R30.2 U2.44 | length 646.4
  Top1 w10: P1.2 535,-275 v1(683,-275) R30.2
  Signal2 w4: v1(683,-275) 714,-306 834,-306 912,-228 v1(912,-174)
  Bottom4 w4: U2.44 911.93,-92.64 912,-92.71 912,-130.09 911.93,-130.16 911.93,-173.93 v1(912,-174)
VBUS: D1.1 R22.1 U5.7 U5.8 USB1.A4 USB1.A9 USB1.B4 USB1.B9 | length 1384
  Top1 w10: v1(-13,0) v1(13,0) ; USB1.A9 175.63,9.61 163.82,21.42 ; USB1.B4 163.82,21.42 ; USB1.B9 161.4,198.58 ; USB1.A4 173.21,210.39 161.4,198.58 ; v1(13,0) 53,40 53,204 86,237 113,237 122,228 122,210 133.42,198.58 161.4,198.58 ; v1(13,0) v1(38,0) v1(64,0) 97,0 118.42,21.42 163.82,21.42
  Bottom4 w10: v1(-13,0) -46,-33 -46,-357 -35,-368 -13,-368 R22.1 U5.7@45.94,-309.06 ; R22.1@13.5,-338.5 U5.8
  Bottom4 w20: v1(-13,0) D1.1 v1(13,0) v1(38,0) v1(64,0)
VCC_1V2: C1.1 C2.1 C3.2 C23.2 L1.2 R1.2 T3.0 U2.22 U2.35 U2.71 | length 2854.1
  Top1 w15: v1(-34,249) -40,255 v1(-40,272) -40,315 5,360 302,360 349,313 349,126 387,88 387,34 348,-5 348,-43 373,-68 397,-68 465,0 v1(465,60)
  Signal2 w10: v1@-40,255 v1(-34,249)
  Signal2 w15: v1@-40,255 v1(-40,272)
  Bottom4 w4: v1(-40,272) -40,321 0,361 174,361 261,274 273,274 282,283 298,283 T3.0 ; C3.2 445,30 445,4 451.36,-2.36 U2.71
  Bottom4 w6: U2.71 561.64,-2.36 569,5 569,235.91 588.09,255 862,255 ; U2.22@885,291.57 885,269 871,255 862,255 ; U2.22 885.35,311.07 891,316.72 C23.2 C23.2@888,345 ; U2.35 896.62,76.38 885,88 885,107 862,130 862,255
  Bottom4 w10: L1.2@-30.28,90.28 L1.2 -5,100.28 -5,150 R1.2 C1.1 C2.1
  Bottom4 w15: v1(-40,272) -40,255 v1(-34,249) C2.1
VCC_2V5: C19.1 C20.1 C25.2 C26.2 C27.1 L3.2 R10.2 R19.1 T1.0 U2.30 U2.31 U2.32 U2.34 U2.36 | length 1653.4
  Top1 w15: v1(405,159) v1(405,181) ; v1(1010,284) v1(1010,306)
  Signal2 w15: v1(405,159) v1(405,181) 955,181 1010,236 v1(1010,284) v1(1010,306)
  Bottom4 w4: T1.0 375.28,269.72 L3.2
  Bottom4 w6: U2.36 937.63,60.63 ; U2.34 939.87,92.13 947,85 947,70 937.63,60.63 ; U2.32 U2.30 935.12,155.12 951,171 951,181 957,187 993,187 C25.2 ; R19.1 990,115 990,50 983,43 955.26,43 937.63,60.63
  Bottom4 w15: L3.2 355,210 315,170 R10.2 C19.1 C20.1 391,145 v1(405,159) v1(405,181) ; R19.1 C25.2 C26.2 C27.1 v1(1010,284) v1(1010,306)
VCC_3V3: 1.4 C7.1 C8.1 C12.1 C13.1 C14.2 C15.2 C17.1 C21.1 C22.1 C28.2 C31.1 L2.2 P3.4 R4.2 R6.2 R8.2 R13.1 R14.1 R15.1 R16.1 R17.1 R20.1 R23.2 R25.2 R26.2 R27.2 R28.2 R30.1 R35.2 T2.0 TF1.4 U2.4 U2.5 U2.20 U2.50 U2.67 U3.3 U4.4 U4.5 | length 4848.4
  Top1 w4: R20.1 R23.2 280,-280 280,-215 R27.2
  Top1 w6: P3.4 R20.1 ; R35.2 1255,95 1255,157 1275,177 R28.2 R26.2 R25.2
  Top1 w10: v1(393,-33) 393,-30 v1(375,-12) 433.82,46.82 433.82,232.18 v1(401,265) 460,324 v1(602,324) 602,298 621,279 796,279 846,329 v1(846,357) ; 1.4 1172.32,7.32 v1(1199,34)
  Top1 w15: R30.1 695,-331 707,-343 758,-343 777.6,-323.4 U4.4 U4.5 ; v1(883,-175) 883,-206 904,-227 v1(965,-227) ; U3.3 975.94,-200 C17.1 ; C28.2 v1(1275,58) R35.2
  Signal2 w10: v1(291,-195) v1(442,-195) 520,-195 v1(550,-225)
  Signal2 w15: v1(375,-12) 393,-30 v1(393,-33) ; v1(767,-280) 821,-280 883,-218 v1(883,-175) ; v1(965,-227) 983,-209 1310,-209 1400,-119 1400,53 1375,78 1295,78 v1(1275,58) 1223,58 v1(1199,34)
  Bottom4 w4: T2.0 401,284 v1(401,265) ; U2.50 806.61,-106.61 C21.1
  Bottom4 w6: C7.1 479,-125 528.07,-75.93 U2.67 ; U2.5 U2.4 601.89,333.11 C14.2 C15.2 C15.2@617.64,342.64 ; v1(846,357) 846,321 853.86,313.14 U2.20
  Bottom4 w10: v1(291,-195) v1(442,-195) 442,-148 C7.1 C8.1 445,-70 445,-37 428,-20 R6.2 ; v1(375,-12) 375,-15 375.28,-15.28 v1(393,-33) ; C21.1 840,-145 C22.1
  Bottom4 w15: R8.2 C12.1 C13.1 ; L2.2 375.28,-15.28 375.28,5.28 C13.1 ; R6.2 R4.2 C13.1 ; R14.1 R13.1 R17.1 R16.1 R15.1 735,-260 C31.1 765,-278 v1(767,-280) ; v1(883,-175) 883,-183 927,-227 v1(965,-227) ; TF1.4 1186.39,46.61 v1(1199,34) 1223,58 v1(1275,58)
VCC_5V: 1.2 C4.2 C34.2 D1.2 P3.3 P4.1 U1.7 U1.8 U1.9 U1.10 U1.16 U1.18 U1.19 | length 3083.3
  Top1 w6: P3.3 240,-450 1320,-450 1352,-418 1352,-149.76 P4.1 1332.24,-130 C34.2 1192.8,-47.8 1.2
  Top1 w10: v1(101,39) 116.47,54.47 v1(116.47,55.47)
  Signal2 w15: v1(124,174) 124,62 v1(101,39) 101,-100 200,-199 P3.3 ; v1(1315,-152) v1(1315,-123)
  Bottom4 w6: v1(124,174) 118,180 118,191 130,203 160,203 166.02,196.98 U1.18 U1.19
  Bottom4 w10: C4.2 73,172 122,172 v1(124,174) 124,176 125.52,177.52 U1.16 ; 118,29 111,29 v1(101,39) 101,40 v1(116.47,55.47) U1.10 ; 118,29 132,29 ; 118,29 97.34,8.34 D1.2 103,0 132,29 ; 118,29 134.53,45.53 U1.10 ; 132,29 137,29 ; U1.10 U1.9 ; 137,29 150.28,42.28 U1.9 ; 137,29 157,29 ; U1.9 U1.8 ; 157,29 171,29 181.77,39.77 U1.7 U1.8 ; 157,29 166.02,38.02 U1.8
  Bottom4 w15: v1(1315,-152) v1(1315,-123)
pads on no net: 1.1 1.13 P4.MH1 P4.MH2 U2.13 U2.14 U2.15 U2.16 U2.17 U2.72 U2.75 U2.76 U2.77 U2.78 U2.84 U2.85 U2.86 U5.1 U5.2 U5.6 U5.10 U5.11 U5.12 U5.13 U5.14 U5.15 U5.16 U5.17 U5.18 U5.19 U5.20 U5.21 U5.22 U5.23 U5.24 U5.27 U5.28 USB1.0 USB1.A8 USB1.B8
copper on no net:
  other v2: 1508.39,-116.77 1508.39,197.4

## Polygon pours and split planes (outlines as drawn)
GND on Gnd3 "GND_L03_P002" (solid, remove dead copper, pour order 2): -100,500 1800,500 1800,-500 -100,-500
GND on Top1 "GND_L01_P000" (solid, remove dead copper, pour order 0): -100,500 1800,500 1800,-500 -100,-500
GND on Signal2 "GND_L02_P001" (solid, remove dead copper, pour order 1): -100,500 1800,500 1800,-500 -100,-500
GND on Bottom4 "GND_L04_P003" (solid, remove dead copper, pour order 3): -100,500 1800,500 1800,-500 -100,-500

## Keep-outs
Keep-Out Layer:
  the board outline again, w10

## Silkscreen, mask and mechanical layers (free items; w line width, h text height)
Top Overlay:
  text "#OTG" at 350,-250 h70
  text "128x80" at 680.04,-385.09 h55 r90
  text "OLED" at 629.01,-410.46 h80 r90
Bottom Overlay:
  rectangle: 550,-314 1029,-301
  text "PD2" at 390.04,473.6 h40 r90
  text "Tx1" at 490.04,473.6 h40 r90
  text "Rx1" at 590.04,473.6 h40 r90
  text "PD5" at 690.04,473.6 h40 r90
  text "PD6" at 790.04,473.6 h40 r90
  text "TX2" at 890.04,473.6 h40 r90
  text "SPK" at 5.38,400.04 h40 r180
  text "PD0" at 136.4,400.04 h40 r180
  text "PD1" at 236.4,400.04 h40 r180
  text "Rx2" at 936.4,400.04 h40 r180
  text "PD12" at 1036.4,400.04 h40 r180
  text "PD19" at 1131.31,400.04 h40 r180
  text "SCK2" at 1241.31,400.04 h40 r180
  text "SDA2" at 1336.4,400.04 h40 r180
  text "PD18" at 1436.4,400.04 h40 r180
  text "PD20" at 1536.4,400.04 h40 r180
  text "PD21" at 1636.4,400.04 h40 r180
  text "TF-Card" at 1662.55,-54.43 h70 r270
  text "Planck-Pi" at 524.08,-216.68 h50
  text "> DevKit" at 567.99,-278.39 h60
  text "F1C200s" at 950.99,-286.5 h80 r270
  text "5V" at 263.6,-400.04 h40
  text "3V3" at 363.6,-400.04 h40
  text "MOSI0" at 458.69,-400.04 h40
  text "MISO0" at 568.69,-400.04 h40
  text "CS0" at 663.6,-400.04 h40
  text "CLK0" at 763.6,-400.04 h40
  text "TX1" at 863.6,-400.04 h40
  text "TX2" at 963.6,-400.04 h40
  text "TY1" at 1063.6,-400.04 h40
  text "TY2" at 1163.6,-400.04 h40
  text "PWM" at 1263.6,-400.04 h40
  text "CS1" at 1363.6,-400.04 h40
  text "MOSI1" at 1463.6,-400.04 h40
  text "CLK1" at 1563.6,-400.04 h40
  text "MISO1" at 1663.6,-400.04 h40
  text "ADC" at 1744.62,-400.04 h40
  text "GND" at 113.6,-405.04 h40
Bottom Solder:
  text "GND" at 306.65,294.01 h23
  text "1V2" at 346.65,294.01 h23
  text "2V5" at 386.65,294.01 h23
  text "3V3" at 426.65,294.01 h23
Mechanical 1:
  the board outline again, w10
